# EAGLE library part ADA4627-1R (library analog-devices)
36 V, 19 MHz, Low Noise, Low Bias Current, JFET Operational Amplifier Source: http://www.analog.com/static/imported-files/data_sheets/ADA4627-1.pdf
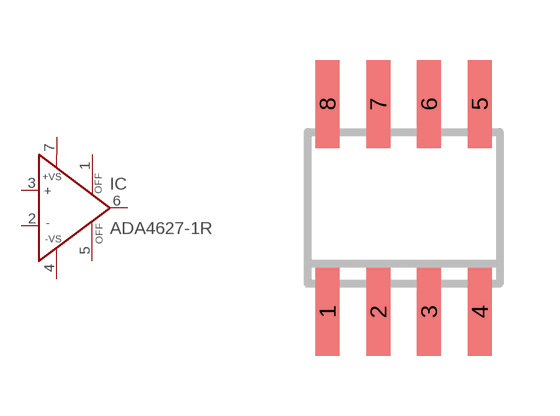
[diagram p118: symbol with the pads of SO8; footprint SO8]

Designator prefix IC

## ADA4627-1R (MPN: ADA4627-1ARZ; OC_FARNELL: 1827378; OC_NEWARK: 26R2398)  [SO8]
1  OFF  pas
2  IN-  in
3  IN+  in
4  -VS  in
5  OFF  pas
6  OUT  out
7  +VS  in

## Footprint SO8 (pad centres in mm)
8-Lead Small Outline IC (SO-8) Source: http://www.analog.com/UploadedFiles/Data_Sheets/703465986AD8611_2_0.pdf
smd 0.6 x 2.2: 1 -1.905,-2.6; 2 -0.635,-2.6; 3 0.635,-2.6; 4 1.905,-2.6; 5 1.905,2.6; 6 0.635,2.6; 7 -0.635,2.6; 8 -1.905,2.6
